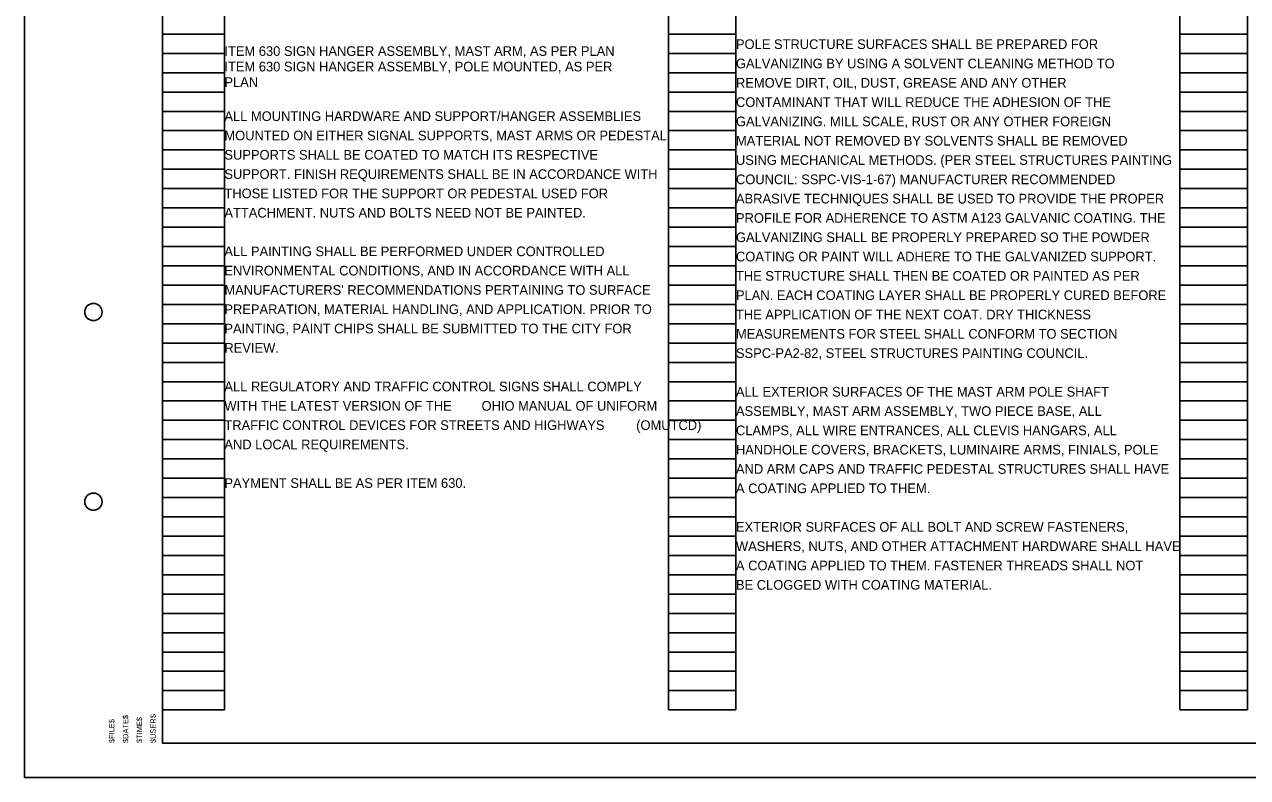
# Model space of a CAD drawing. Extents: x -27 to 74, y -37 to 38.
# Drawn here: x -0.51 to 17.23, y -7.51 to 3.41 of the extents above; entities that cross this region are included whole.
import ezdxf

# ---------------------------------------------------------------- set-up
doc = ezdxf.new("R2010")
doc.units = 0
for name, color, linetype in [('PF_P_Text', 7, 'Continuous'), ('SC_Scratch1', 7, 'Continuous'), ('SH_Cut_Line', 7, 'Continuous'), ('SH_Data', 7, 'Continuous'), ('SH_Text', 7, 'Continuous'), ('TX_P_Misc', 7, 'Continuous')]:
    doc.layers.add(name, color=color, linetype=linetype)

msp = doc.modelspace()

# ---------------------------------------------------------------- linework, layer by layer
at = {"layer": 'PF_P_Text'}
msp.add_lwpolyline([(1.494, 13.992), (32.994, 13.992), (32.994, -7.008), (1.494, -7.008)], close=True, dxfattribs=at)
for centre in [(0.494, -0.758), (0.494, -3.508)]:
    msp.add_circle(centre, 0.125, dxfattribs=at)
at = {"layer": 'SC_Scratch1'}
for p, q in [((1.494, -6.528), (1.494, 13.632)), ((2.394, -6.528), (2.394, 13.632)), ((8.834, -6.528), (8.834, 13.632)), ((9.814, -6.528), (9.814, 13.632)), ((16.254, -6.528), (16.254, 13.632)), ((17.234, -6.528), (17.234, 13.632)), ((1.494, 3.272), (2.394, 3.272)), ((8.834, 3.272), (9.814, 3.272)), ((16.254, 3.272), (17.234, 3.272)), ((1.494, 2.992), (2.394, 2.992)), ((8.834, 2.992), (9.814, 2.992)), ((16.254, 2.992), (17.234, 2.992)), ((1.494, 2.712), (2.394, 2.712)), ((8.834, 2.712), (9.814, 2.712)), ((16.254, 2.712), (17.234, 2.712)), ((1.494, 2.432), (2.394, 2.432)), ((8.834, 2.432), (9.814, 2.432)), ((16.254, 2.432), (17.234, 2.432)), ((1.494, 2.152), (2.394, 2.152)), ((8.834, 2.152), (9.814, 2.152)), ((16.254, 2.152), (17.234, 2.152)), ((1.494, 1.872), (2.394, 1.872)), ((8.834, 1.872), (9.814, 1.872)), ((16.254, 1.872), (17.234, 1.872)), ((1.494, 1.592), (2.394, 1.592)), ((8.834, 1.592), (9.814, 1.592)), ((16.254, 1.592), (17.234, 1.592)), ((1.494, 1.312), (2.394, 1.312)), ((8.834, 1.312), (9.814, 1.312)), ((16.254, 1.312), (17.234, 1.312)), ((1.494, 1.032), (2.394, 1.032)), ((8.834, 1.032), (9.814, 1.032)), ((16.254, 1.032), (17.234, 1.032)), ((1.494, 0.752), (2.394, 0.752)), ((8.834, 0.752), (9.814, 0.752)), ((16.254, 0.752), (17.234, 0.752)), ((1.494, 0.472), (2.394, 0.472)), ((8.834, 0.472), (9.814, 0.472)), ((16.254, 0.472), (17.234, 0.472)), ((1.494, 0.192), (2.394, 0.192)), ((8.834, 0.192), (9.814, 0.192)), ((16.254, 0.192), (17.234, 0.192)), ((1.494, -0.088), (2.394, -0.088)), ((8.834, -0.088), (9.814, -0.088)), ((16.254, -0.088), (17.234, -0.088)), ((1.494, -0.368), (2.394, -0.368)), ((8.834, -0.368), (9.814, -0.368)), ((16.254, -0.368), (17.234, -0.368)), ((1.494, -0.648), (2.394, -0.648)), ((8.834, -0.648), (9.814, -0.648)), ((16.254, -0.648), (17.234, -0.648)), ((1.494, -0.928), (2.394, -0.928)), ((8.834, -0.928), (9.814, -0.928)), ((16.254, -0.928), (17.234, -0.928)), ((1.494, -1.208), (2.394, -1.208)), ((8.834, -1.208), (9.814, -1.208)), ((16.254, -1.208), (17.234, -1.208)), ((1.494, -1.488), (2.394, -1.488)), ((8.834, -1.488), (9.814, -1.488)), ((16.254, -1.488), (17.234, -1.488)), ((1.494, -1.768), (2.394, -1.768)), ((8.834, -1.768), (9.814, -1.768)), ((16.254, -1.768), (17.234, -1.768)), ((1.494, -2.048), (2.394, -2.048)), ((8.834, -2.048), (9.814, -2.048)), ((16.254, -2.048), (17.234, -2.048)), ((1.494, -2.328), (2.394, -2.328)), ((8.834, -2.328), (9.814, -2.328)), ((16.254, -2.328), (17.234, -2.328)), ((1.494, -2.608), (2.394, -2.608)), ((8.834, -2.608), (9.814, -2.608)), ((16.254, -2.608), (17.234, -2.608)), ((1.494, -2.888), (2.394, -2.888)), ((8.834, -2.888), (9.814, -2.888)), ((16.254, -2.888), (17.234, -2.888)), ((1.494, -3.168), (2.394, -3.168)), ((8.834, -3.168), (9.814, -3.168)), ((16.254, -3.168), (17.234, -3.168)), ((1.494, -3.448), (2.394, -3.448)), ((8.834, -3.448), (9.814, -3.448)), ((16.254, -3.448), (17.234, -3.448)), ((1.494, -3.728), (2.394, -3.728)), ((8.834, -3.728), (9.814, -3.728)), ((16.254, -3.728), (17.234, -3.728)), ((1.494, -4.008), (2.394, -4.008)), ((8.834, -4.008), (9.814, -4.008)), ((16.254, -4.008), (17.234, -4.008)), ((1.494, -4.288), (2.394, -4.288)), ((8.834, -4.288), (9.814, -4.288)), ((16.254, -4.288), (17.234, -4.288)), ((1.494, -4.568), (2.394, -4.568)), ((8.834, -4.568), (9.814, -4.568)), ((16.254, -4.568), (17.234, -4.568)), ((1.494, -4.848), (2.394, -4.848)), ((8.834, -4.848), (9.814, -4.848)), ((16.254, -4.848), (17.234, -4.848)), ((1.494, -5.128), (2.394, -5.128)), ((8.834, -5.128), (9.814, -5.128)), ((16.254, -5.128), (17.234, -5.128)), ((1.494, -5.408), (2.394, -5.408)), ((8.834, -5.408), (9.814, -5.408)), ((16.254, -5.408), (17.234, -5.408)), ((1.494, -5.688), (2.394, -5.688)), ((8.834, -5.688), (9.814, -5.688)), ((16.254, -5.688), (17.234, -5.688)), ((1.494, -5.968), (2.394, -5.968)), ((8.834, -5.968), (9.814, -5.968)), ((16.254, -5.968), (17.234, -5.968)), ((1.494, -6.248), (2.394, -6.248)), ((8.834, -6.248), (9.814, -6.248)), ((16.254, -6.248), (17.234, -6.248)), ((1.494, -6.528), (2.394, -6.528)), ((8.834, -6.528), (9.814, -6.528)), ((16.254, -6.528), (17.234, -6.528)), ((-0.506, -7.508), (-0.506, -7.508))]:
    msp.add_line(p, q, dxfattribs=at)
at = {"layer": 'SH_Cut_Line'}
msp.add_lwpolyline([(-0.506, -7.508), (33.494, -7.508), (33.494, 14.492), (-0.506, 14.492)], close=True, dxfattribs=at)

# ---------------------------------------------------------------- texts
at = {"layer": 'SH_Data'}
for s, p in [('ITEM 630 SIGN HANGER ASSEMBLY, MAST ARM, AS PER PLAN', (2.394, 2.956)), ('ITEM 630 SIGN HANGER ASSEMBLY, POLE MOUNTED, AS PER ', (2.394, 2.731)), ('PLAN', (2.394, 2.506)), ('ALL MOUNTING HARDWARE AND SUPPORT/HANGER ASSEMBLIES ', (2.394, 2.012)), ('MOUNTED ON EITHER SIGNAL SUPPORTS, MAST ARMS OR PEDESTAL ', (2.394, 1.732)), ('SUPPORTS SHALL BE COATED TO MATCH ITS RESPECTIVE ', (2.394, 1.452)), ('SUPPORT. FINISH REQUIREMENTS SHALL BE IN ACCORDANCE WITH ', (2.394, 1.172)), ('THOSE LISTED FOR THE SUPPORT OR PEDESTAL USED FOR ', (2.394, 0.892)), ('ATTACHMENT. NUTS AND BOLTS NEED NOT BE PAINTED.', (2.394, 0.612)), ('ALL PAINTING SHALL BE PERFORMED UNDER CONTROLLED ', (2.394, 0.052)), ('ENVIRONMENTAL CONDITIONS, AND IN ACCORDANCE WITH ALL ', (2.394, -0.228)), ("MANUFACTURERS' RECOMMENDATIONS PERTAINING TO SURFACE ", (2.394, -0.508)), ('PREPARATION, MATERIAL HANDLING, AND APPLICATION. PRIOR TO ', (2.394, -0.788)), ('PAINTING, PAINT CHIPS SHALL BE SUBMITTED TO THE CITY FOR ', (2.394, -1.068)), ('REVIEW.', (2.394, -1.348)), ('ALL REGULATORY AND TRAFFIC CONTROL SIGNS SHALL COMPLY ', (2.394, -1.908)), ('WITH THE LATEST VERSION OF THE ', (2.394, -2.188)), ('OHIO MANUAL OF UNIFORM ', (6.124, -2.188)), ('TRAFFIC CONTROL DEVICES FOR STREETS AND HIGHWAYS ', (2.394, -2.468)), ('(OMUTCD) ', (8.367, -2.468)), ('AND LOCAL REQUIREMENTS.', (2.394, -2.748)), ('PAYMENT SHALL BE AS PER ITEM 630.', (2.394, -3.308))]:
    msp.add_text(s, height=0.14, dxfattribs=at).set_placement(p)
at = {"layer": 'SH_Text'}
for s, p in [('POLE STRUCTURE SURFACES SHALL BE PREPARED FOR ', (9.814, 3.056)), ('GALVANIZING BY USING A SOLVENT CLEANING METHOD TO ', (9.814, 2.776)), ('REMOVE DIRT, OIL, DUST, GREASE AND ANY OTHER ', (9.814, 2.496)), ('CONTAMINANT THAT WILL REDUCE THE ADHESION OF THE ', (9.814, 2.216)), ('GALVANIZING. MILL SCALE, RUST OR ANY OTHER FOREIGN ', (9.814, 1.936)), ('MATERIAL NOT REMOVED BY SOLVENTS SHALL BE REMOVED ', (9.814, 1.656)), ('USING MECHANICAL METHODS. (PER STEEL STRUCTURES PAINTING ', (9.814, 1.376)), ('COUNCIL: SSPC-VIS-1-67) MANUFACTURER RECOMMENDED ', (9.814, 1.096)), ('ABRASIVE TECHNIQUES SHALL BE USED TO PROVIDE THE PROPER ', (9.814, 0.816)), ('PROFILE FOR ADHERENCE TO ASTM A123 GALVANIC COATING. THE ', (9.814, 0.536)), ('GALVANIZING SHALL BE PROPERLY PREPARED SO THE POWDER ', (9.814, 0.256)), ('COATING OR PAINT WILL ADHERE TO THE GALVANIZED SUPPORT. ', (9.814, -0.024)), ('THE STRUCTURE SHALL THEN BE COATED OR PAINTED AS PER ', (9.814, -0.304)), ('PLAN. EACH COATING LAYER SHALL BE PROPERLY CURED BEFORE ', (9.814, -0.584)), ('THE APPLICATION OF THE NEXT COAT. DRY THICKNESS ', (9.814, -0.864)), ('MEASUREMENTS FOR STEEL SHALL CONFORM TO SECTION ', (9.814, -1.144)), ('SSPC-PA2-82, STEEL STRUCTURES PAINTING COUNCIL.', (9.814, -1.424)), ('ALL EXTERIOR SURFACES OF THE MAST ARM POLE SHAFT ', (9.814, -1.984)), ('ASSEMBLY, MAST ARM ASSEMBLY, TWO PIECE BASE, ALL ', (9.814, -2.264)), ('CLAMPS, ALL WIRE ENTRANCES, ALL CLEVIS HANGARS, ALL ', (9.814, -2.544)), ('HANDHOLE COVERS, BRACKETS, LUMINAIRE ARMS, FINIALS, POLE ', (9.814, -2.824)), ('AND ARM CAPS AND TRAFFIC PEDESTAL STRUCTURES SHALL HAVE ', (9.814, -3.104)), ('A COATING APPLIED TO THEM.  ', (9.814, -3.384)), ('EXTERIOR SURFACES OF ALL BOLT AND SCREW FASTENERS, ', (9.814, -3.944)), ('WASHERS, NUTS, AND OTHER ATTACHMENT HARDWARE SHALL HAVE ', (9.814, -4.224)), ('A COATING APPLIED TO THEM. FASTENER THREADS SHALL NOT ', (9.814, -4.504)), ('BE CLOGGED WITH COATING MATERIAL.', (9.814, -4.784))]:
    msp.add_text(s, height=0.14, dxfattribs=at).set_placement(p)
at = {"layer": 'TX_P_Misc'}
for s, p in [('$FILE$', (0.799, -7.008)), ('$DATE$', (0.999, -7.008)), ('$TIME$', (1.199, -7.008)), ('$USER$', (1.399, -7.008))]:
    msp.add_text(s, height=0.078, rotation=90, dxfattribs=at).set_placement(p)

doc.saveas('drawing.dxf')
